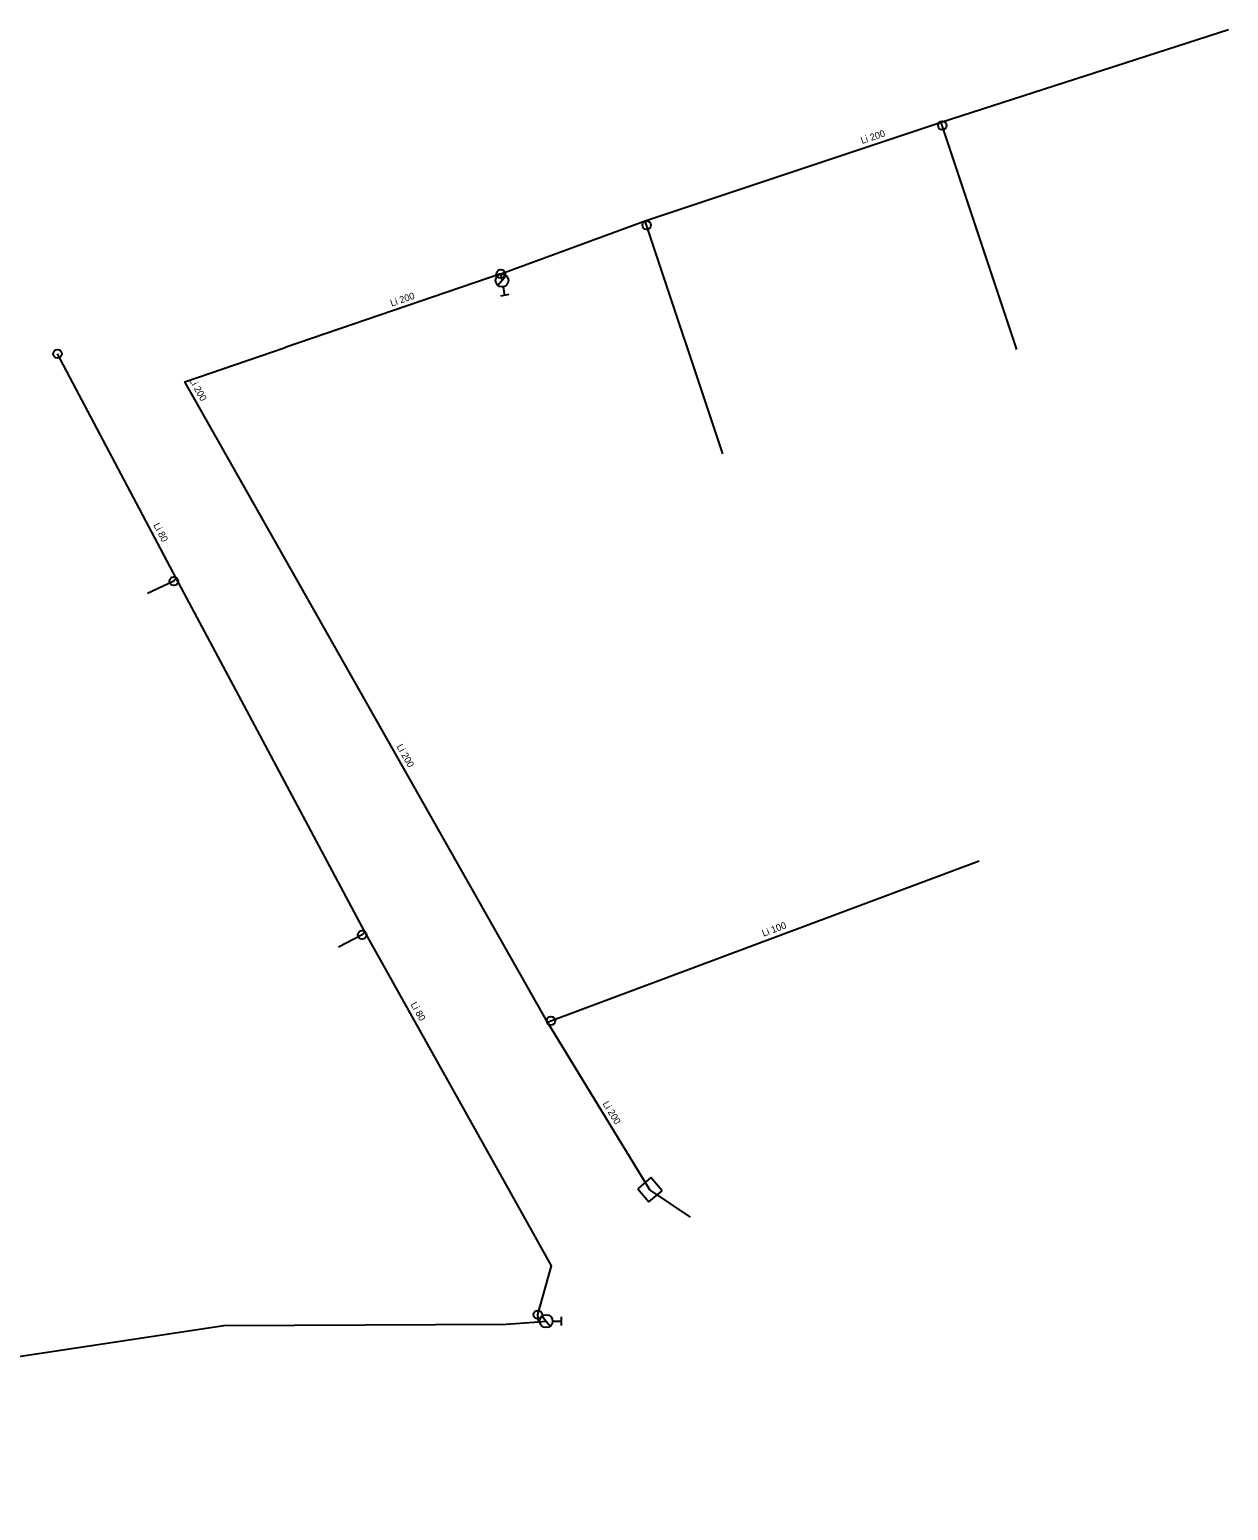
# Model space of a CAD drawing. Extents: x -783658 to -783200, y -1065250 to -1064865.
# Drawn here: x -783270 to -783200.2, y -1065232.8 to -1065146.6 of the extents above; entities that cross this region are included whole.
import ezdxf

# ---------------------------------------------------------------- set-up
doc = ezdxf.new("R2010")
doc.units = 0
for name, color, linetype in [('Hydranty', 7, 'Continuous'), ('Popis vodovodních řadů', 7, 'Continuous'), ('Vod přípojky-voda pitná', 7, 'Continuous'), ('Vodovodní řad', 7, 'Continuous'), ('Vodovodní šachty', 7, 'Continuous'), ('Vodovodní šoupata', 7, 'Continuous')]:
    doc.layers.add(name, color=color, linetype=linetype)

msp = doc.modelspace()

# ---------------------------------------------------------------- linework, layer by layer
at = {"layer": 'Hydranty'}
for p, q in [((-783242.221, -1065160.971), (-783242.721, -1065161.53)), ((-783242.072, -1065162.068), (-783242.564, -1065162.155)), ((-783242.405, -1065161.619), (-783242.318, -1065162.112)), ((-783240.131, -1065221.516), (-783239.668, -1065222.106)), ((-783239.525, -1065221.81), (-783239.025, -1065221.81)), ((-783239.025, -1065221.56), (-783239.025, -1065222.06))]:
    msp.add_line(p, q, dxfattribs=at)
for centre in [(-783242.47, -1065161.25), (-783239.9, -1065221.81)]:
    msp.add_circle(centre, 0.375, dxfattribs=at)
at = {"layer": 'Vod přípojky-voda pitná'}
for points in [[(-783212.5, -1065165.27), (-783216.84, -1065152.23), (-783216.9, -1065152.03)], [(-783229.61, -1065171.33), (-783234.05, -1065158.03), (-783234.13, -1065157.78)], [(-783261.43, -1065178.57), (-783261.57, -1065178.74), (-783263.1, -1065179.47)], [(-783250.45, -1065199.15), (-783250.61, -1065199.33), (-783251.98, -1065200.04)]]:
    msp.add_lwpolyline(points, dxfattribs=at)
at = {"layer": 'Vodovodní řad'}
for points in [[(-783242.54, -1065160.86), (-783234.13, -1065157.78), (-783216.9, -1065152.03), (-783200.186, -1065146.647)], [(-783242.54, -1065160.86), (-783255.09, -1065165.15)], [(-783242.47, -1065161.25), (-783242.54, -1065160.86)], [(-783257.64, -1065185.68), (-783261.43, -1065178.57), (-783268.35, -1065165.51)], [(-783257.86, -1065172.56), (-783260.93, -1065167.14), (-783255.09, -1065165.15)], [(-783239.83, -1065204.41), (-783257.86, -1065172.56)], [(-783240.38, -1065221.43), (-783239.59, -1065218.59), (-783241.3, -1065215.53), (-783250.45, -1065199.15), (-783257.64, -1065185.68)], [(-783239.62, -1065204.33), (-783214.699, -1065195.019)], [(-783239.83, -1065204.41), (-783239.62, -1065204.33)], [(-783233.86, -1065214.16), (-783239.83, -1065204.41)], [(-783231.503, -1065215.751), (-783233.86, -1065214.16)], [(-783329.85, -1065232.82), (-783309.43, -1065229.73), (-783293.99, -1065227.4), (-783258.67, -1065222.06), (-783242.23, -1065221.98), (-783240.34, -1065221.84)], [(-783240.34, -1065221.84), (-783240.38, -1065221.43)], [(-783240.34, -1065221.84), (-783239.9, -1065221.81)]]:
    msp.add_lwpolyline(points, dxfattribs=at)
at = {"layer": 'Vodovodní šachty'}
for p, q in [((-783233.798, -1065213.456), (-783234.564, -1065214.098)), ((-783234.564, -1065214.098), (-783233.922, -1065214.864)), ((-783233.156, -1065214.222), (-783233.798, -1065213.456)), ((-783233.922, -1065214.864), (-783233.156, -1065214.222))]:
    msp.add_line(p, q, dxfattribs=at)
at = {"layer": 'Vodovodní šoupata'}
for centre in [(-783216.84, -1065152.23), (-783234.05, -1065158.03), (-783242.54, -1065160.86), (-783268.35, -1065165.51), (-783261.57, -1065178.74), (-783250.61, -1065199.33), (-783239.62, -1065204.33), (-783240.38, -1065221.43)]:
    msp.add_circle(centre, 0.25, dxfattribs=at)

# ---------------------------------------------------------------- texts
at = {"layer": 'Popis vodovodních řadů'}
for s, rotation, p in [('Li 200', 18.4549, (-783221.514, -1065153.306)), ('Li 200', 18.8721, (-783248.896, -1065162.768)), ('Li 200', 299.52811, (-783260.698, -1065167.043)), ('Li 80', 297.91742, (-783262.783, -1065175.483)), ('Li 200', 299.51381, (-783248.627, -1065188.362)), ('Li 100', 20.48597, (-783227.247, -1065199.44)), ('Li 80', 299.18808, (-783247.806, -1065203.37)), ('Li 200', 301.47946, (-783236.632, -1065209.154))]:
    msp.add_text(s, height=0.4, rotation=rotation, dxfattribs=at).set_placement(p)

doc.saveas('drawing.dxf')
